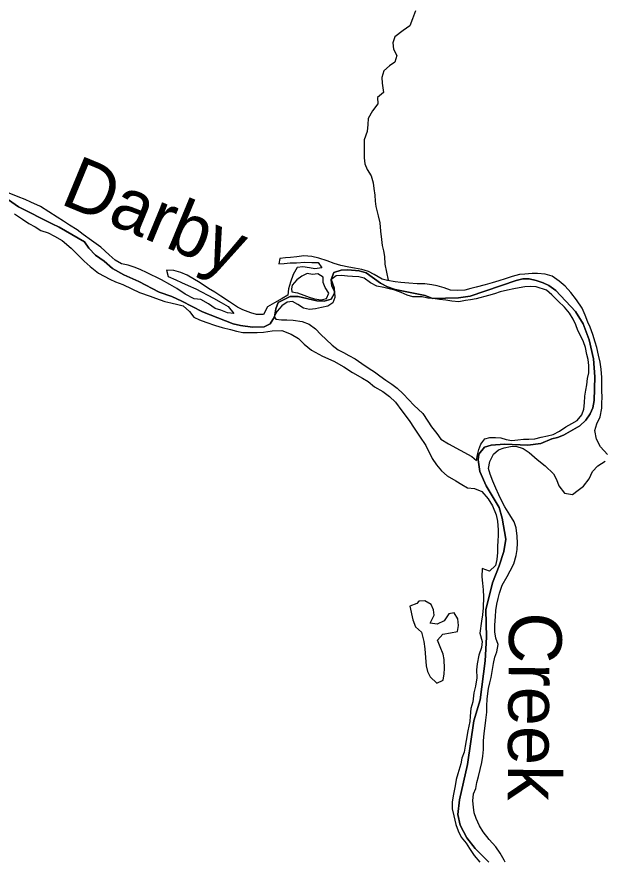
# Model space of a CAD drawing. Extents: x 114604 to 551442, y 316898 to 567001.
# Drawn here: x 161190 to 166736, y 317643 to 325659 of the extents above; entities that cross this region are included whole.
import ezdxf

# ---------------------------------------------------------------- set-up
doc = ezdxf.new("R2010")
doc.units = 0
for name, color, linetype in [('DV_X_County_Line', 7, 'Continuous'), ('GE_P_Alignment_500_Distances', 7, 'Continuous'), ('MT_X_Edge_Line', 7, 'Continuous'), ('PM_P_Cells', 7, 'Continuous'), ('RD_P_GR_Rt', 7, 'Continuous')]:
    doc.layers.add(name, color=color, linetype=linetype)

msp = doc.modelspace()

# ---------------------------------------------------------------- linework, layer by layer
at = {"layer": 'DV_X_County_Line'}
msp.add_line((163792.2, 323080.9), (163796.4, 323052.9), dxfattribs=at)
for points in [[(163122.7, 323009.3), (163064.5, 323047.2), (163006.4, 323083.1), (162926.1, 323137), (162801.8, 323208.8), (162743.7, 323234.7), (162677.5, 323254.6), (162607.5, 323258.4), (162621.7, 323198.4), (162695.8, 323164.5), (162749.9, 323140.6), (162812.1, 323112.7), (162884.3, 323078.8), (162938.4, 323050.9), (163000.5, 323021), (163052.7, 322993.1), (163124.9, 322951.3), (163191, 322913.4), (163247.3, 322847.4), (163185.2, 322851.3), (163121.1, 322877.2), (163069, 322895.1), (163006.8, 322939), (162932.6, 322978.8), (162868.5, 322986.7), (162784.3, 323030.5), (162704.1, 323084.4), (162639.9, 323122.3), (162559.7, 323166.2), (162419.3, 323235.9), (162365.2, 323259.8), (162309.1, 323283.7), (162245, 323303.6), (162180.9, 323317.4), (162120.7, 323353.3), (162064.5, 323403.3), (161984.2, 323475.2), (161898, 323537), (161817.7, 323596.9), (161759.5, 323638.8), (161687.3, 323684.7), (161631.2, 323720.6), (161571, 323758.5), (161490.8, 323810.4), (161412.5, 323860.3), (161322.3, 323902.1), (161266.2, 323928), (161200.1, 323953.9), (161115.9, 323985.8)], [(161166.5, 323791.6), (161242.7, 323739.7), (161302.9, 323699.8), (161361, 323667.9), (161417.2, 323634), (161485.3, 323610.2), (161545.5, 323578.3), (161617.7, 323538.4), (161704, 323464.5), (161826.4, 323342.6), (161884.7, 323290.7), (161962.9, 323228.8), (162069.2, 323171), (162125.3, 323147.1), (162193.5, 323121.2), (162277.6, 323081.4), (162351.8, 323045.5), (162452, 323009.7), (162504.1, 322991.8), (162590.3, 322960), (162648.4, 322946.1), (162714.5, 322932.3), (162766.6, 322918.4), (162826.8, 322864.4), (162865, 322812.5), (162921.1, 322786.6), (162981.3, 322762.7), (163071.4, 322732.9), (163135.6, 322713), (163213.7, 322693.2), (163269.8, 322679.3), (163329.9, 322665.4), (163466, 322665.7), (163528.1, 322667.9), (163608.1, 322682.1), (163702.2, 322684.3), (163790.4, 322650.5), (163858.6, 322608.6), (163912.8, 322554.7), (163983, 322496.8), (164087.3, 322441), (164193.5, 322395.2), (164289.8, 322339.3), (164372, 322287.5), (164464.3, 322233.6), (164518.4, 322199.7), (164578.6, 322151.8), (164656.8, 322107.9), (164721, 322060), (164779.2, 322006.1), (164837.5, 321924.2)], [(166786.7, 321508.4), (166722.4, 321582.3), (166684.2, 321654.3), (166667.9, 321736.4), (166685.7, 321798.5), (166717.6, 321866.7), (166735.4, 321948.8), (166735.2, 321998.8), (166737.1, 322048.9), (166734.9, 322117), (166734.7, 322175.1), (166732.5, 322239.1), (166726.3, 322319.2), (166718.1, 322383.3), (166703.9, 322451.3), (166685.6, 322523.4), (166671.5, 322573.4), (166647.3, 322647.4), (166623, 322715.4), (166600.9, 322765.4), (166576.6, 322831.5), (166548.4, 322897.5), (166494.1, 322975.4), (166439.9, 323045.4), (166385.7, 323105.3), (166329.5, 323153.3), (166263.3, 323199.1), (166197.1, 323219), (166125.1, 323226.8), (166073, 323224.7), (166003, 323220.5), (165952.9, 323214.4), (165882.9, 323196.2), (165816.9, 323174), (165758.9, 323155.9), (165694.9, 323137.7), (165628.9, 323119.5), (165542.9, 323097.3), (165492.8, 323083.1), (165436.8, 323067), (165366.8, 323064.8), (165298.7, 323068.7), (165240.6, 323088.5), (165174.4, 323108.4), (165122.4, 323118.3), (165056.3, 323128.1), (164982.2, 323128), (164904.1, 323133.8), (164830, 323139.6), (164773.9, 323145.5), (164703.8, 323159.3), (164651.7, 323173.2), (164575.5, 323217.1), (164521.4, 323243), (164459.3, 323264.9), (164389.2, 323274.7), (164337.1, 323284.6), (164259, 323302.4), (164196.9, 323320.3), (164130.7, 323346.2), (164052.6, 323370), (163986.5, 323387.9), (163908.4, 323391.7), (163844.3, 323383.5), (163784.3, 323377.4), (163734.3, 323373.2), (163680.2, 323369.1), (163672.4, 323317), (163722.4, 323319.2), (163780.4, 323325.3), (163840.5, 323327.4), (163918.6, 323331.6), (163984.6, 323329.8), (164046.7, 323329.9), (164080.9, 323278), (164014.8, 323269.8), (163962.8, 323277.7), (163898.7, 323287.5), (163846.6, 323283.4), (163808.8, 323217.2), (163783, 323143.1), (163765.1, 323081), (163757.3, 323018.9), (163705.3, 322988.7), (163631.4, 322946.5), (163563.4, 322908.3), (163527.6, 322838.1), (163459.5, 322835.9), (163405.4, 322851.8), (163331.3, 322879.7), (163279.2, 322907.6), (163204.9, 322957.5), (163122.7, 323009.3)], [(164719, 323079.6), (164666.8, 323093.2), (164602.7, 323104.8), (164542.4, 323136.4), (164480, 323182), (164429.9, 323193.6), (164371.8, 323197.2), (164321.8, 323200.9), (164267.7, 323206.5), (164215.6, 323204.1), (164165.9, 323165.7), (164170.3, 323107.7), (164198.7, 323055.8), (164203.1, 322997.8), (164185.5, 322947.6), (164135.6, 322917.2), (164077.7, 322902.8), (164019.8, 322890.3), (163961.7, 322883.9), (163907.6, 322897.5), (163853.3, 322931.2), (163801.1, 322960.8), (163751.1, 322952.5), (163701.3, 322920.1), (163657.6, 322869.7), (163627.9, 322817.4), (163644.1, 322791.5)], [(163796.4, 323052.9), (163850.5, 323041.3), (163908.7, 323019.7), (163960.9, 323000), (164011.1, 322986.4), (164073.2, 322974.8), (164125.1, 322989.2), (164146.8, 323039.4), (164112.4, 323091.2), (164094, 323141.2), (164093.6, 323191.2), (164041.4, 323222.9), (163991.4, 323216.5), (163941.3, 323224.1), (163891.4, 323199.8), (163841.6, 323165.4), (163800, 323115), (163792.2, 323080.9)], [(165500.4, 321490.6), (165547.4, 321451.7), (165557, 321505.8), (165568.6, 321556), (165588.3, 321606.2), (165623.9, 321658.5), (165673.9, 321668.9), (165725.9, 321671.3), (165776, 321665.6), (165826.2, 321649.9), (165882.3, 321642.3), (165936.3, 321646.7), (165990.3, 321653.1), (166042.3, 321655.5), (166100.3, 321657.9), (166160.3, 321672.4), (166220.2, 321684.8), (166274.2, 321699.2), (166332, 321731.7), (166391.7, 321770.1), (166449.6, 321802.6), (166499.4, 321831), (166545, 321885.4), (166564.7, 321937.6), (166570.3, 321997.7), (166571.8, 322061.8), (166583.4, 322117.9), (166593, 322170.1), (166598.6, 322230.2), (166610.2, 322284.3), (166611.7, 322352.4), (166603.3, 322408.4), (166593, 322458.4), (166578.5, 322522.3), (166560.1, 322576.3), (166535.7, 322632.2), (166507.2, 322686), (166488.8, 322739.9), (166462.4, 322791.8), (166426, 322849.6), (166381.6, 322907.3), (166321.1, 322963), (166260.6, 323022.6), (166210.3, 323066.3), (166110, 323097.6), (166057.9, 323103.2), (166003.9, 323098.8), (165949.9, 323088.4), (165899.9, 323080.1), (165840, 323067.6), (165770, 323051.1), (165716.1, 323032.7), (165660.2, 323018.3), (165544.3, 322985.4), (165490.3, 322975), (165440.3, 322970.6), (165378.4, 322958.2), (165312.3, 322961.7), (165256.2, 322971.3), (165194.1, 322978.9), (165135.9, 322988.5), (165083.9, 322992.1), (165029.8, 323003.7), (164943.7, 323003.1), (164889.5, 323018.7), (164831.3, 323044.3), (164773.1, 323065.9), (164719, 323079.6)], [(163644.1, 322791.5), (163696.2, 322785.9), (163748.3, 322786.3), (163808.4, 322782.7), (163892.5, 322771.3), (163960.8, 322743.7), (164019.1, 322700.1), (164069.5, 322646.4), (164121.9, 322598.7), (164176.4, 322547.1), (164234.7, 322501.4), (164284.9, 322475.8), (164337.2, 322448.1), (164395.5, 322416.5), (164459.8, 322372.9), (164528.2, 322325.4), (164578.5, 322291.7), (164630.8, 322254), (164685.2, 322214.4), (164743.5, 322176.7), (164793.8, 322137.1), (164850.2, 322085.4), (164904.7, 322027.7), (164953.1, 321976), (165035.7, 321898.5), (165084.3, 321824.8), (165120.7, 321771), (165169.2, 321709.3), (165207.6, 321653.5), (165280, 321610), (165500.4, 321490.6)], [(164837.5, 321924.2), (164907.9, 321830.2), (164956.1, 321758.2), (165006.4, 321684.3), (165064.7, 321594.3), (165127.1, 321470.3), (165167.4, 321410.3), (165215.6, 321354.4), (165267.8, 321306.5), (165350, 321258.6), (165408.1, 321224.7), (165460.3, 321192.8), (165526.4, 321186.9), (165596.5, 321157.1), (165656.8, 321089.1), (165697, 321023.2), (165731.3, 320937.2), (165745.5, 320875.1), (165751.7, 320795), (165751.9, 320741), (165748, 320690.9), (165744.2, 320636.8), (165744.3, 320580.8), (165738.5, 320514.7), (165724.7, 320456.6), (165668.8, 320402.4), (165598.6, 320428.2), (165596.8, 320350.1), (165603, 320288.1), (165609.2, 320224), (165611.4, 320160), (165609.7, 320053.8), (165601.9, 319989.7), (165592.1, 319927.6), (165578.4, 319815.5), (165598.6, 319735.4), (165594.8, 319677.3), (165569, 319605.2), (165551.2, 319525.1), (165547.4, 319467), (165547.6, 319390.9), (165535.8, 319310.8), (165522, 319248.7), (165510.2, 319162.5), (165492.4, 319100.4), (165486.6, 319028.3), (165482.7, 318978.2), (165464.9, 318888.1), (165449.2, 318796), (165439.4, 318743.9), (165427.5, 318685.8), (165407.7, 318627.7), (165397.8, 318575.6), (165370, 318481.4), (165354.2, 318425.3), (165344.3, 318367.2), (165326.6, 318287.1), (165314.8, 318215), (165314.9, 318148.9), (165331.2, 318080.8), (165349.4, 318000.8), (165371.6, 317940.8), (165401.8, 317880.8), (165448, 317822.8), (165478.2, 317772.8), (165522.4, 317704.9), (165576.7, 317643.4)], [(165816.7, 317643.4), (165808.8, 317661.5), (165770.6, 317729.5), (165728.4, 317787.5), (165666.1, 317857.4), (165607.9, 317931.3), (165573.7, 317987.3), (165541.4, 318055.3), (165525.3, 318109.3), (165517.1, 318163.4), (165510.9, 318225.4), (165518.7, 318289.5), (165538.6, 318341.7), (165550.5, 318397.7), (165564.3, 318455.8), (165596, 318588.1), (165605.8, 318648.2), (165611.6, 318710.3), (165613.4, 318792.3), (165619.2, 318864.5), (165627, 318936.6), (165634.8, 318988.6), (165642.6, 319064.7), (165644.4, 319126.8), (165648.3, 319188.9), (165654.1, 319241), (165660, 319291), (165671.8, 319343.1), (165685.7, 319395.2), (165695.6, 319451.3), (165707.4, 319525.4), (165719.2, 319585.5), (165739.1, 319637.7), (165750.9, 319705.8), (165730.7, 319765.8), (165718.5, 319827.8), (165718.3, 319889.9), (165726.1, 319974), (165729.9, 320028.1), (165737.7, 320088.2), (165751.6, 320144.3), (165763.5, 320194.4), (165789.3, 320268.5), (165835.1, 320350.7), (165865, 320404.9), (165898.8, 320471), (165922.6, 320551.2), (165930.4, 320609.2), (165934.3, 320669.3), (165930.1, 320735.4), (165921.8, 320813.5), (165901.6, 320871.5), (165861.4, 320937.5), (165815.1, 321011.4), (165785, 321067.4), (165756.8, 321125.4), (165730.6, 321189.4), (165700.3, 321257.5), (165674.1, 321321.5), (165660, 321375.5), (165671.8, 321441.6), (165705.6, 321511.8), (165755.5, 321553.9), (165807.5, 321572.1), (165867.5, 321586.2), (165917.6, 321586.4), (165987.7, 321564.5), (166043.9, 321526.6), (166122.2, 321460.7), (166196.4, 321400.8), (166276.7, 321326.9), (166304.9, 321270.9), (166325.1, 321210.9), (166381.3, 321141)], [(166381.3, 321141), (166455.5, 321129.2), (166509.4, 321169.3), (166561.3, 321209.5), (166615.2, 321279.7), (166647, 321347.9), (166694.9, 321400), (166764.8, 321444.3)]]:
    msp.add_lwpolyline(points, dxfattribs=at)
at = {"layer": 'GE_P_Alignment_500_Distances'}
for points in [[(165664.3, 317643.4), (165533.5, 317772.5), (165453.1, 317874.4), (165392.7, 317994.4), (165368.4, 318094.4), (165384, 318232.6), (165461.1, 318569.2), (165522, 318983.8), (165579.5, 319182.2), (165628.4, 319552.8), (165639.8, 319775.1), (165633.1, 320037.3), (165696.4, 320291.8), (165762, 320454.2), (165805.6, 320590.4), (165825.3, 320706.6), (165790.7, 320904.8), (165760.4, 321006.8), (165637.7, 321212.8), (165577.2, 321348.8), (165560.8, 321458.9), (165566.7, 321512.9), (165620.6, 321577.1), (165684.6, 321597.3), (165810.7, 321607.6), (166032.9, 321596.2), (166155, 321614.5), (166259, 321656.8), (166313, 321668.9), (166371, 321691.1), (166524.9, 321781.6), (166580.8, 321833.8), (166624.7, 321893.9), (166648.5, 321952.1), (166660.3, 322022.2), (166667.7, 322244.5), (166655.2, 322414.7), (166614.6, 322596.8), (166556.1, 322746.8), (166485.7, 322864.8), (166299, 323064.6), (166230.8, 323110.4), (166178.6, 323138.4), (166112.5, 323160.2), (166046.4, 323174.1), (165984.3, 323173.9), (165922.3, 323159.8), (165486.3, 323010.5), (165376.3, 322994.2), (165128, 322989.6), (165059.9, 323015.5), (164775.4, 323072.9), (164701.3, 323098.7), (164635.1, 323134.6), (164498.7, 323230.4), (164432.6, 323250.3), (164326.4, 323260), (164262.4, 323257.9), (164194.4, 323233.7), (164168.5, 323167.5), (164196.8, 323089.5), (164200.9, 323039.5), (164167.1, 322983.3), (164103.1, 322963.1), (164033, 322966.9), (163854.7, 323008.6), (163780.6, 323008.4), (163666.7, 322950.1), (163642.8, 322889.9), (163631, 322815.8), (163591.2, 322749.6), (163533.2, 322719.5), (163423.1, 322717.2), (163308.9, 322730.9), (163240.8, 322748.8), (162948.2, 322862.2), (162753.7, 322963.9), (162659.5, 323007.7), (162537.3, 323047.5), (162344.8, 323149.1), (162202.5, 323212.8), (162094.2, 323272.7), (162015.3, 323341.2), (161935.6, 323400.4), (161871.4, 323466.4), (161829.2, 323524.3), (161590.5, 323666), (161522.4, 323695.8), (161203.6, 323857.3), (161109.3, 323923.1)], [(161109.3, 323923.1), (161203.6, 323857.3), (161522.4, 323695.8), (161590.5, 323666), (161829.2, 323524.3), (161871.4, 323466.4), (161935.6, 323400.4), (162015.3, 323341.2), (162094.2, 323272.7), (162202.5, 323212.8), (162344.8, 323149.1), (162537.3, 323047.5), (162659.5, 323007.7), (162753.7, 322963.9), (162948.2, 322862.2), (163240.8, 322748.8), (163308.9, 322730.9), (163423.1, 322717.2), (163533.2, 322719.5), (163591.2, 322749.6), (163631, 322815.8), (163642.8, 322889.9), (163666.7, 322950.1), (163780.6, 323008.4), (163854.7, 323008.6), (164033, 322966.9), (164103.1, 322963.1), (164167.1, 322983.3), (164200.9, 323039.5), (164196.8, 323089.5), (164168.5, 323167.5), (164194.4, 323233.7), (164262.4, 323257.9), (164326.4, 323260), (164432.6, 323250.3), (164498.7, 323230.4), (164635.1, 323134.6), (164701.3, 323098.7), (164775.4, 323072.9), (165059.9, 323015.5), (165128, 322989.6), (165376.3, 322994.2), (165486.3, 323010.5), (165922.3, 323159.8), (165984.3, 323173.9), (166046.4, 323174.1), (166112.5, 323160.2), (166178.6, 323138.4), (166230.8, 323110.4), (166299, 323064.6), (166485.7, 322864.8), (166556.1, 322746.8), (166614.6, 322596.8), (166655.2, 322414.7), (166667.7, 322244.5), (166660.3, 322022.2), (166648.5, 321952.1), (166624.7, 321893.9), (166580.8, 321833.8), (166524.9, 321781.6), (166371, 321691.1), (166313, 321668.9), (166259, 321656.8), (166155, 321614.5), (166032.9, 321596.2), (165810.7, 321607.6), (165684.6, 321597.3), (165620.6, 321577.1), (165566.7, 321512.9), (165560.8, 321458.9), (165577.2, 321348.8), (165637.7, 321212.8), (165760.4, 321006.8), (165790.7, 320904.8), (165825.3, 320706.6), (165805.6, 320590.4), (165762, 320454.2), (165696.4, 320291.8), (165633.1, 320037.3), (165639.8, 319775.1), (165628.4, 319552.8), (165579.5, 319182.2), (165522, 318983.8), (165461.1, 318569.2), (165384, 318232.6), (165368.4, 318094.4), (165392.7, 317994.4), (165453.1, 317874.4), (165533.5, 317772.5), (165664.3, 317643.4)]]:
    msp.add_lwpolyline(points, dxfattribs=at)
at = {"layer": 'MT_X_Edge_Line'}
for points in [[(164981, 320094.3), (164915, 320070.2), (164943.1, 319941.2)], [(164943.1, 319941.2), (164967.6, 319874), (165025.8, 319824.1), (165048.1, 319734.1), (165056.3, 319666), (165062.5, 319583.9), (165068.8, 319505.9), (165080.9, 319451.8), (165107.1, 319401.8), (165171.4, 319339.9), (165229.3, 319370.1), (165239.2, 319430.2), (165243, 319480.3), (165238.8, 319564.3), (165230.6, 319616.4), (165200.4, 319684.4), (165176.2, 319748.4), (165228.1, 319804.6), (165300.1, 319816.8), (165366.1, 319831), (165376, 319887.1), (165367.8, 319949.1), (165333.6, 320007.1), (165283.6, 319999), (165239.7, 319930.8), (165171.7, 319898.6), (165107.6, 319910.4), (165145.5, 319984.6), (165137.3, 320036.6), (165117.1, 320086.7), (165057, 320120.5), (164998.9, 320116.4), (164981, 320094.3)]]:
    msp.add_lwpolyline(points, dxfattribs=at)
at = {"layer": 'PM_P_Cells'}
msp.add_lwpolyline([(164968.7, 325715.2), (164938.9, 325641), (164915.1, 325572.9), (164851.1, 325530.7), (164771.2, 325468.4), (164753.4, 325414.3), (164759.6, 325352.2), (164789.8, 325294.2), (164771.9, 325230.1), (164722, 325193.9), (164668.1, 325147.7), (164648.2, 325083.6), (164652.4, 325029.5), (164664.7, 324941.5), (164606.7, 324895.3), (164610.9, 324835.2), (164561.1, 324767), (164519.2, 324694.8), (164517.4, 324638.7), (164509.6, 324572.6), (164479.8, 324492.4), (164482, 324426.4), (164480.1, 324372.3), (164482.3, 324322.2), (164486.4, 324264.2), (164510.6, 324210.2), (164546.8, 324152.2), (164567, 324084.1), (164573.2, 324032.1), (164581.4, 323968), (164585.6, 323912), (164591.7, 323861.9), (164614, 323771.9), (164630.2, 323705.8), (164636.4, 323625.7), (164646.7, 323547.7), (164652.8, 323491.6), (164663, 323441.6), (164673.1, 323387.5), (164677.4, 323313.4), (164708.4, 323161.6)], dxfattribs=at)

# ---------------------------------------------------------------- texts
at = {"layer": 'RD_P_GR_Rt'}
for s, height, rotation, p in [('Darby', 500.03, 337.52614, (161587.7, 323890.4)), ('Creek', 500, 269.52812, (165856, 320013.8))]:
    msp.add_text(s, height=height, rotation=rotation, dxfattribs=at).set_placement(p)

doc.saveas('drawing.dxf')
